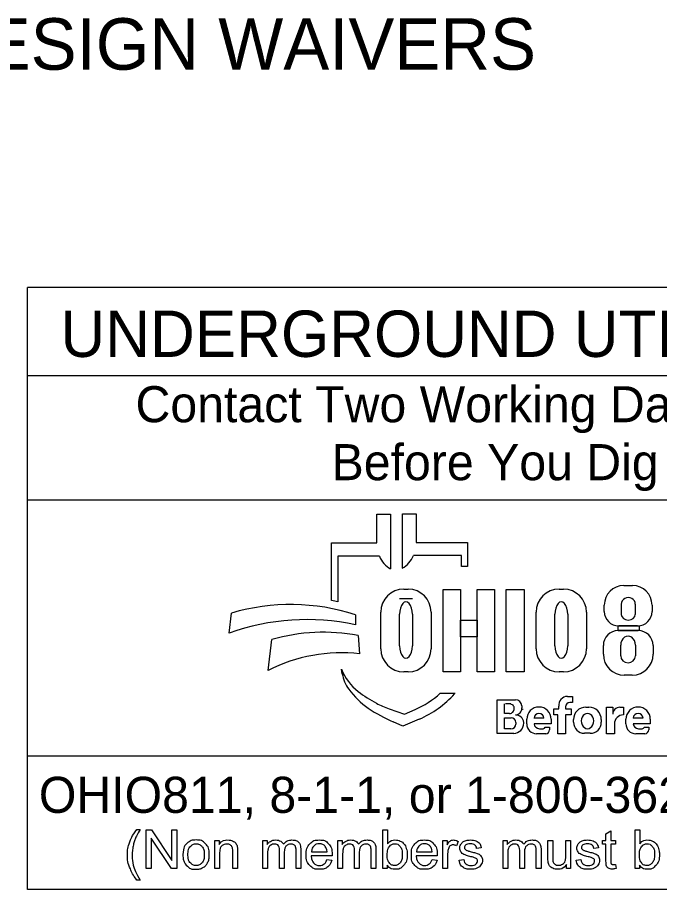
# Model space of a CAD drawing. Extents: x 0 to 34, y 0 to 22.
# Drawn here: x 2.939 to 5.431, y 2.143 to 5.529 of the extents above; entities that cross this region are included whole.
import ezdxf

# ---------------------------------------------------------------- set-up
doc = ezdxf.new("R2010")
doc.units = 0
doc.layers.add('SH_Data', color=7, linetype='Continuous')
doc.layers.add('SH_Text', color=7, linetype='Continuous')

msp = doc.modelspace()

# ---------------------------------------------------------------- linework, layer by layer
at = {"layer": 'SH_Data'}
for p, q in [((2.9775, 2.1428), (2.9775, 4.4803)), ((7.2275, 4.4803), (2.9775, 4.4803)), ((2.9775, 4.1387), (7.2275, 4.1387)), ((2.9775, 3.6553), (7.2275, 3.6553)), ((7.2275, 2.6607), (2.9775, 2.6607)), ((7.2275, 2.1428), (2.9775, 2.1428))]:
    msp.add_line(p, q, dxfattribs=at)
at = {"layer": 'SH_Text'}
for p, q in [((4.3335, 3.4883), (4.3335, 3.5998)), ((4.3335, 3.5998), (4.3872, 3.5998)), ((4.3872, 3.5998), (4.3872, 3.3877)), ((4.4329, 3.39), (4.4329, 3.6021)), ((4.4329, 3.6021), (4.4865, 3.6021)), ((4.4865, 3.6021), (4.4865, 3.4906)), ((4.1576, 3.2644), (4.1576, 3.4883)), ((4.1576, 3.4883), (4.3335, 3.4883)), ((4.4865, 3.4906), (4.6857, 3.4906)), ((4.6857, 3.4906), (4.6857, 3.3968)), ((4.1828, 3.4369), (4.1828, 3.26)), ((4.3439, 3.4369), (4.1828, 3.4369)), ((4.6625, 3.4392), (4.4761, 3.4392)), ((4.6625, 3.3968), (4.6625, 3.4392)), ((4.6857, 3.3968), (4.6625, 3.3968)), ((5.2931, 3.3231), (5.3258, 3.3231)), ((4.4385, 3.3091), (4.4551, 3.3091)), ((5.0416, 3.3091), (5.0581, 3.3091)), ((4.4718, 3.2721), (4.422, 3.2721)), ((5.283, 3.2111), (5.283, 3.2504)), ((5.3371, 3.2504), (5.3371, 3.2111)), ((4.3491, 3.0776), (4.3491, 3.2196)), ((4.5445, 3.2196), (4.5445, 3.0776)), ((4.9521, 3.0776), (4.9521, 3.2196)), ((5.1476, 3.2196), (5.1476, 3.0776)), ((5.2168, 3.2225), (5.2168, 3.2468)), ((5.4022, 3.2468), (5.4022, 3.2225)), ((3.7602, 3.1381), (3.7696, 3.2162)), ((4.2509, 3.2097), (4.2509, 3.1709)), ((4.422, 3.089), (4.422, 3.2114)), ((4.4718, 3.2114), (4.4718, 3.089)), ((5.025, 3.089), (5.025, 3.2114)), ((5.0748, 3.2114), (5.0748, 3.089)), ((5.3462, 3.1665), (5.2728, 3.1665)), ((4.2608, 3.1291), (4.2671, 3.0582)), ((5.271, 3.1482), (5.3483, 3.1482)), ((3.912, 2.9936), (3.9267, 3.1137)), ((5.2131, 3.0563), (5.2131, 3.0903)), ((5.2806, 3.0503), (5.2806, 3.0912)), ((5.3374, 3.0912), (5.3374, 3.0503)), ((5.4062, 3.0903), (5.4062, 3.0563)), ((4.1997, 2.9807), (4.1967, 2.9986)), ((4.4551, 2.9882), (4.4385, 2.9882)), ((5.0581, 2.9882), (5.0416, 2.9882)), ((5.3252, 2.9753), (5.2941, 2.9753)), ((4.58, 2.9048), (4.6375, 2.9048)), ((4.8013, 2.749), (4.8013, 2.8798)), ((4.8013, 2.8798), (4.8725, 2.8798)), ((5.0739, 2.8926), (5.0934, 2.8926)), ((5.0934, 2.8926), (5.0934, 2.8696)), ((4.3816, 2.8444), (4.441, 2.8239)), ((4.8293, 2.8263), (4.8293, 2.8632)), ((4.8545, 2.8632), (4.8332, 2.8632)), ((4.8963, 2.856), (4.8963, 2.8481)), ((5.0213, 2.8212), (5.0213, 2.8442)), ((5.0213, 2.8442), (5.0406, 2.8442)), ((5.0406, 2.8442), (5.0406, 2.8546)), ((5.0667, 2.8526), (5.0667, 2.8442)), ((5.0667, 2.8442), (5.0883, 2.8442)), ((5.0934, 2.8691), (5.0832, 2.8691)), ((5.0883, 2.8442), (5.0883, 2.8212)), ((5.1451, 2.8508), (5.1573, 2.8508)), ((5.2254, 2.7478), (5.2254, 2.8505)), ((5.2254, 2.8505), (5.2499, 2.8505)), ((5.2499, 2.8505), (5.2499, 2.8237)), ((5.2772, 2.8505), (5.291, 2.8505)), ((5.291, 2.8505), (5.291, 2.8209)), ((4.441, 2.8239), (4.4821, 2.8417)), ((4.8487, 2.8263), (4.8293, 2.8263)), ((5.0362, 2.8212), (5.0213, 2.8212)), ((5.0362, 2.7478), (5.0362, 2.8212)), ((5.0883, 2.8212), (5.0667, 2.8212)), ((5.0667, 2.8212), (5.0667, 2.7478)), ((4.435, 2.7769), (4.3976, 2.7934)), ((4.4983, 2.8044), (4.435, 2.7769)), ((4.8293, 2.7669), (4.8293, 2.8097)), ((4.8293, 2.8097), (4.8548, 2.8097)), ((4.8729, 2.7916), (4.8729, 2.7853)), ((4.9043, 2.7887), (4.9043, 2.7884)), ((4.9159, 2.7858), (4.9159, 2.8042)), ((4.9824, 2.8082), (4.9439, 2.8082)), ((5.0104, 2.7866), (4.944, 2.7866)), ((5.0104, 2.8042), (5.0104, 2.7866)), ((5.0973, 2.7922), (5.0973, 2.8029)), ((5.2051, 2.8029), (5.2051, 2.7922)), ((5.2559, 2.786), (5.2559, 2.7478)), ((5.3008, 2.7858), (5.3008, 2.8042)), ((5.3674, 2.8082), (5.3288, 2.8082)), ((5.3953, 2.7866), (5.3289, 2.7866)), ((5.3953, 2.8042), (5.3953, 2.7866)), ((4.865, 2.749), (4.8013, 2.749)), ((4.8546, 2.7669), (4.8293, 2.7669)), ((4.9892, 2.7478), (4.9538, 2.7478)), ((4.9649, 2.7673), (4.979, 2.7673)), ((4.9876, 2.7729), (5.0045, 2.7729)), ((5.0045, 2.7729), (5.0045, 2.7631)), ((5.0667, 2.7478), (5.0362, 2.7478)), ((5.1623, 2.7494), (5.1401, 2.7494)), ((5.2559, 2.7478), (5.2254, 2.7478)), ((5.3742, 2.7478), (5.3388, 2.7478)), ((5.3498, 2.7673), (5.3639, 2.7673)), ((5.3725, 2.7729), (5.3894, 2.7729)), ((5.3894, 2.7729), (5.3894, 2.7631))]:
    msp.add_line(p, q, dxfattribs=at)
for points in [[(4.591, 3.3081), (4.6589, 3.3081), (4.6589, 2.9881), (4.591, 2.9881)], [(4.7231, 3.3081), (4.7911, 3.3081), (4.7911, 2.9881), (4.7231, 2.9881)], [(4.8364, 3.3081), (4.9052, 3.3081), (4.9052, 2.9881), (4.8364, 2.9881)], [(4.6589, 3.1882), (4.7231, 3.1882), (4.7231, 3.1242), (4.6589, 3.1242)], [(5.2706, 3.1665), (5.3523, 3.1665), (5.3523, 3.1481), (5.2706, 3.1481)]]:
    msp.add_lwpolyline(points, close=True, dxfattribs=at)
for points in [[(3.4021, 2.3766), (3.4153, 2.3766)], [(3.4389, 2.2239), (3.4389, 2.3741), (3.4592, 2.3741), (3.5382, 2.2561), (3.5382, 2.3741), (3.5572, 2.3741), (3.5572, 2.2239), (3.5369, 2.2239), (3.4579, 2.3419), (3.4579, 2.2239), (3.4389, 2.2239)], [(4.3743, 2.2239), (4.3573, 2.2239), (4.3573, 2.3741), (4.3757, 2.3741), (4.3757, 2.3206)], [(5.2233, 2.2558), (5.2233, 2.3185), (5.2097, 2.3185), (5.2097, 2.3328), (5.2233, 2.3328), (5.2233, 2.3597), (5.2417, 2.3708), (5.2417, 2.3328), (5.2601, 2.3328), (5.2601, 2.3185), (5.2417, 2.3185), (5.2417, 2.2547)], [(5.3534, 2.2239), (5.3363, 2.2239), (5.3363, 2.3741), (5.3548, 2.3741), (5.3548, 2.3206)], [(3.7048, 2.2239), (3.7048, 2.3328), (3.7214, 2.3328), (3.7214, 2.3173)], [(3.8912, 2.2239), (3.8912, 2.3328), (3.9077, 2.3328), (3.9077, 2.3174)], [(4.1826, 2.2239), (4.1826, 2.3328), (4.1991, 2.3328), (4.1991, 2.3174)], [(4.5904, 2.2239), (4.5904, 2.3328), (4.607, 2.3328), (4.607, 2.3163)], [(4.6495, 2.3293), (4.643, 2.3122)], [(4.7394, 2.3046), (4.7213, 2.3022)], [(4.8236, 2.2239), (4.8236, 2.3328), (4.8401, 2.3328), (4.8401, 2.3174)], [(4.9979, 2.2654), (4.9979, 2.3328), (5.0164, 2.3328), (5.0164, 2.2724)], [(5.0676, 2.2745), (5.0676, 2.3328), (5.0861, 2.3328), (5.0861, 2.2239), (5.0696, 2.2239)], [(5.194, 2.3046), (5.1759, 2.3022)], [(3.7233, 2.2833), (3.7233, 2.2239), (3.7048, 2.2239)], [(3.7932, 2.2908), (3.7932, 2.2239), (3.7748, 2.2239), (3.7748, 2.2901)], [(3.9097, 2.2803), (3.9097, 2.2239), (3.8912, 2.2239)], [(3.9743, 2.2871), (3.9743, 2.2239), (3.9559, 2.2239), (3.9559, 2.2946)], [(4.0388, 2.2986), (4.0388, 2.2239), (4.0203, 2.2239), (4.0203, 2.2924)], [(4.16, 2.2736), (4.0788, 2.2736)], [(4.0799, 2.2887), (4.1406, 2.2887)], [(4.201, 2.2803), (4.201, 2.2239), (4.1826, 2.2239)], [(4.2657, 2.2871), (4.2657, 2.2239), (4.2473, 2.2239), (4.2473, 2.2946)], [(4.3301, 2.2986), (4.3301, 2.2239), (4.3117, 2.2239), (4.3117, 2.2924)], [(4.568, 2.2736), (4.4868, 2.2736)], [(4.4879, 2.2887), (4.5486, 2.2887)], [(4.6088, 2.2809), (4.6088, 2.2239), (4.5904, 2.2239)], [(4.842, 2.2803), (4.842, 2.2239), (4.8236, 2.2239)], [(4.9067, 2.2871), (4.9067, 2.2239), (4.8883, 2.2239), (4.8883, 2.2946)], [(4.9711, 2.2986), (4.9711, 2.2239), (4.9527, 2.2239), (4.9527, 2.2924)], [(4.1404, 2.2591), (4.1595, 2.2567)], [(4.3743, 2.2375), (4.3743, 2.2239)], [(4.5484, 2.2591), (4.5675, 2.2567)], [(4.653, 2.2564), (4.6712, 2.2593)], [(5.0696, 2.2239), (5.0696, 2.24)], [(5.1076, 2.2564), (5.1258, 2.2593)], [(5.2601, 2.2404), (5.2628, 2.2241)], [(5.3534, 2.2375), (5.3534, 2.2239)], [(3.4153, 2.1798), (3.4021, 2.1798)]]:
    msp.add_lwpolyline(points, dxfattribs=at)
for centre, radius, start, end in [((4.4353, 3.4736), 0.0985, 201.9296, 240.7469), ((4.3847, 3.476), 0.0985, 299.2531, 338.0704), ((5.2931, 3.2468), 0.0763, 90, 180), ((5.3258, 3.2468), 0.0763, 0, 90), ((4.4385, 3.2196), 0.0895, 90, 180), ((4.4551, 3.2196), 0.0895, 0, 90), ((5.0416, 3.2196), 0.0895, 90, 180), ((5.0581, 3.2196), 0.0895, 0, 90), ((4.0295, 2.4554), 0.8191, 79.2074, 81.0007), ((3.9997, 2.4302), 0.8191, 72.1402, 106.3144), ((5.2728, 3.2225), 0.056, 180, 270), ((5.3462, 3.2225), 0.056, 270, 0), ((4.0628, 2.2991), 0.8919, 77.8238, 109.8274), ((4.1267, 2.4094), 0.7322, 79.44, 105.8467), ((5.271, 3.0903), 0.0579, 90, 180), ((5.3483, 3.0903), 0.0579, 0, 90), ((4.1987, 2.4262), 0.6357, 83.8248, 116.8021), ((4.4385, 3.0776), 0.0895, 180, 270), ((4.4551, 3.0776), 0.0895, 270, 0), ((5.0416, 3.0776), 0.0895, 180, 270), ((5.0581, 3.0776), 0.0895, 270, 0), ((5.2941, 3.0563), 0.081, 180, 270), ((5.3252, 3.0563), 0.081, 270, 0), ((4.3841, 3.0707), 0.2008, 201.0457, 232.5314), ((4.341, 3.0048), 0.1433, 189.6817, 216.0884), ((4.4747, 3.1022), 0.3088, 216.0884, 235.7167), ((4.5766, 3.3219), 0.5173, 232.5314, 241.794), ((4.3387, 3.1722), 0.3602, 293.4582, 312.0712), ((4.3387, 3.1722), 0.401, 293.4582, 317.8286), ((4.8725, 2.856), 0.0238, 0, 90), ((5.0739, 2.859), 0.0335, 90, 187.5187), ((4.6412, 3.3465), 0.6044, 235.7167, 246.2325), ((4.4914, 3.1631), 0.3371, 241.794, 250.9821), ((4.8487, 2.845), 0.0187, 270, 2.0582), ((4.8505, 2.8463), 0.0169, 357.8325, 90), ((4.8721, 2.8453), 0.0243, 270, 6.6529), ((4.9631, 2.8042), 0.0473, 0, 180), ((5.0832, 2.8526), 0.0165, 90, 180), ((5.1451, 2.8029), 0.0478, 90, 180), ((5.1573, 2.8029), 0.0478, 0, 90), ((5.2768, 2.8237), 0.0269, 89.2449, 180), ((5.3481, 2.8042), 0.0473, 0, 180), ((4.8722, 2.7889), 0.0321, 4.0748, 90), ((4.8827, 2.8438), 0.0175, 347.4023, 0), ((4.9632, 2.8072), 0.0193, 2.9632, 177.0368), ((5.2908, 2.786), 0.0349, 89.6033, 180), ((5.3481, 2.8072), 0.0193, 2.9632, 177.0368), ((4.8546, 2.7853), 0.0184, 270, 0), ((4.8548, 2.7916), 0.0181, 0, 90), ((4.865, 2.7884), 0.0393, 270, 0), ((4.8714, 2.7887), 0.033, 0, 11.7502), ((4.9538, 2.7858), 0.038, 180, 270), ((4.9649, 2.7883), 0.021, 184.827, 270), ((5.1401, 2.7922), 0.0428, 180, 270), ((5.1623, 2.7922), 0.0428, 270, 0), ((5.3388, 2.7858), 0.038, 180, 270), ((5.3498, 2.7883), 0.021, 184.827, 270), ((4.979, 2.7767), 0.00938, 270, 335.9979), ((4.9892, 2.7631), 0.0152, 270, 0), ((5.3639, 2.7767), 0.00938, 270, 335.9979), ((5.3742, 2.7631), 0.0152, 270, 0)]:
    msp.add_arc(centre, radius, start, end, dxfattribs=at)
for centre, major_axis, ratio, start_param, end_param in [((4.4469, 3.2114), (0, 0.0484), 0.514403, 4.712389, 7.853982), ((5.0499, 3.2114), (0, 0.0484), 0.514403, 4.712389, 7.853982), ((5.31, 3.2504), (0.0271, 0), 0.969373, 0, 3.141593), ((5.31, 3.2111), (0.0271, 0), 0.818453, 3.141593, 6.283185), ((5.309, 3.0912), (0, 0.0358), 0.794529, 4.712389, 7.853982), ((4.4469, 3.089), (0, 0.0484), 0.514403, 1.570796, 4.712389), ((5.0499, 3.089), (0, 0.0484), 0.514403, 1.570796, 4.712389), ((5.309, 3.0503), (0.0284, 0), 0.959837, 3.141593, 6.283185), ((5.1517, 2.7976), (0, 0.029), 0.832186, 4.712389, 7.853982), ((5.1517, 2.7976), (0, 0.0302), 0.797287, 1.570796, 4.712389)]:
    msp.add_ellipse(centre, major_axis=major_axis, ratio=ratio, start_param=start_param, end_param=end_param, dxfattribs=at)
for points in [[(3.4021, 2.1798), (3.3869, 2.199), (3.3763, 2.2248), (3.3657, 2.2506), (3.3657, 2.2783), (3.3657, 2.3026), (3.3736, 2.325), (3.3829, 2.3509), (3.4021, 2.3766)], [(3.4153, 2.3766), (3.4029, 2.3553), (3.3989, 2.3462), (3.3927, 2.332), (3.3891, 2.3167), (3.3847, 2.2975), (3.3847, 2.2782), (3.3847, 2.2289), (3.4153, 2.1798)], [(3.5814, 2.2783), (3.5814, 2.3085), (3.5981, 2.3231), (3.6122, 2.3352), (3.6323, 2.3352), (3.6547, 2.3352), (3.669, 2.3205), (3.6832, 2.3058), (3.6832, 2.2799), (3.6832, 2.2589), (3.6769, 2.2469), (3.6706, 2.2348), (3.6586, 2.2282), (3.6466, 2.2215), (3.6323, 2.2215), (3.6095, 2.2215), (3.5954, 2.2362), (3.5814, 2.2508), (3.5814, 2.2783)], [(3.6003, 2.2783), (3.6003, 2.2574), (3.6094, 2.247), (3.6185, 2.2366), (3.6323, 2.2366), (3.646, 2.2366), (3.6551, 2.2471), (3.6642, 2.2575), (3.6642, 2.279), (3.6642, 2.2991), (3.6551, 2.3095), (3.6459, 2.3199), (3.6323, 2.3199), (3.6185, 2.3199), (3.6094, 2.3096), (3.6003, 2.2992), (3.6003, 2.2783)], [(3.7214, 2.3173), (3.7334, 2.3352), (3.756, 2.3352), (3.7659, 2.3352), (3.7741, 2.3316), (3.7823, 2.3281), (3.7864, 2.3224), (3.7905, 2.3166), (3.7922, 2.3087), (3.7932, 2.3036), (3.7932, 2.2908)], [(3.7748, 2.2901), (3.7748, 2.3013), (3.7726, 2.3069), (3.7705, 2.3125), (3.765, 2.3158), (3.7595, 2.3191), (3.7521, 2.3191), (3.7404, 2.3191), (3.7318, 2.3117), (3.7233, 2.3042), (3.7233, 2.2833)], [(3.9077, 2.3174), (3.9128, 2.3254), (3.9214, 2.3303), (3.9299, 2.3352), (3.9407, 2.3352), (3.9528, 2.3352), (3.9606, 2.3301), (3.9683, 2.3251), (3.9715, 2.3161), (3.9844, 2.3352), (4.0051, 2.3352), (4.0213, 2.3352), (4.03, 2.3262), (4.0388, 2.3172), (4.0388, 2.2986)], [(3.9559, 2.2946), (3.9559, 2.3069), (3.9514, 2.313), (3.9469, 2.3191), (3.9366, 2.3191), (3.9288, 2.3191), (3.9222, 2.315), (3.9156, 2.311), (3.9126, 2.3031), (3.9097, 2.2952), (3.9097, 2.2803)], [(4.0203, 2.2924), (4.0203, 2.3035), (4.0185, 2.3083), (4.0168, 2.3132), (4.012, 2.3162), (4.0073, 2.3191), (4.001, 2.3191), (3.9895, 2.3191), (3.9819, 2.3115), (3.9743, 2.3039), (3.9743, 2.2871)], [(4.1595, 2.2567), (4.155, 2.24), (4.1428, 2.2307), (4.1306, 2.2215), (4.1117, 2.2215), (4.0878, 2.2215), (4.0738, 2.2362), (4.0598, 2.2509), (4.0598, 2.2774), (4.0598, 2.3049), (4.074, 2.32), (4.0881, 2.3352), (4.1106, 2.3352), (4.1324, 2.3352), (4.1463, 2.3203), (4.1601, 2.3055), (4.1601, 2.2785), (4.1601, 2.2769), (4.16, 2.2736)], [(4.1406, 2.2887), (4.1394, 2.3025), (4.1337, 2.3094), (4.1249, 2.3201), (4.1108, 2.3201), (4.0981, 2.3201), (4.0894, 2.3115), (4.0808, 2.303), (4.0799, 2.2887)], [(4.1991, 2.3174), (4.2042, 2.3254), (4.2127, 2.3303), (4.2212, 2.3352), (4.2321, 2.3352), (4.2442, 2.3352), (4.2519, 2.3301), (4.2597, 2.3251), (4.2628, 2.3161), (4.2758, 2.3352), (4.2965, 2.3352), (4.3127, 2.3352), (4.3214, 2.3262), (4.3301, 2.3172), (4.3301, 2.2986)], [(4.2473, 2.2946), (4.2473, 2.3069), (4.2428, 2.313), (4.2383, 2.3191), (4.228, 2.3191), (4.2202, 2.3191), (4.2136, 2.315), (4.207, 2.311), (4.204, 2.3031), (4.201, 2.2952), (4.201, 2.2803)], [(4.3117, 2.2924), (4.3117, 2.3035), (4.3099, 2.3083), (4.3081, 2.3132), (4.3034, 2.3162), (4.2987, 2.3191), (4.2923, 2.3191), (4.2809, 2.3191), (4.2733, 2.3115), (4.2657, 2.3039), (4.2657, 2.2871)], [(4.3741, 2.2792), (4.3741, 2.2596), (4.3794, 2.2509), (4.3881, 2.2366), (4.4029, 2.2366), (4.415, 2.2366), (4.4238, 2.2471), (4.4326, 2.2576), (4.4326, 2.2784), (4.4326, 2.2998), (4.4241, 2.3099), (4.4157, 2.3201), (4.4038, 2.3201), (4.3917, 2.3201), (4.3829, 2.3096), (4.3741, 2.299), (4.3741, 2.2792)], [(4.3757, 2.3206), (4.3874, 2.3352), (4.4055, 2.3352), (4.4155, 2.3352), (4.4245, 2.3311), (4.4335, 2.3271), (4.4392, 2.3198), (4.445, 2.3124), (4.4483, 2.3021), (4.4516, 2.2918), (4.4516, 2.28), (4.4516, 2.252), (4.4378, 2.2368), (4.4239, 2.2215), (4.4046, 2.2215), (4.3853, 2.2215), (4.3743, 2.2375)], [(4.5675, 2.2567), (4.563, 2.24), (4.5508, 2.2307), (4.5386, 2.2215), (4.5196, 2.2215), (4.4958, 2.2215), (4.4818, 2.2362), (4.4678, 2.2509), (4.4678, 2.2774), (4.4678, 2.3049), (4.482, 2.32), (4.4961, 2.3352), (4.5186, 2.3352), (4.5404, 2.3352), (4.5543, 2.3203), (4.5681, 2.3055), (4.5681, 2.2785), (4.5681, 2.2769), (4.568, 2.2736)], [(4.5486, 2.2887), (4.5474, 2.3025), (4.5417, 2.3094), (4.5328, 2.3201), (4.5188, 2.3201), (4.5061, 2.3201), (4.4974, 2.3115), (4.4888, 2.303), (4.4879, 2.2887)], [(4.607, 2.3163), (4.6133, 2.3278), (4.6187, 2.3315), (4.6241, 2.3352), (4.6305, 2.3352), (4.6398, 2.3352), (4.6495, 2.3293)], [(4.643, 2.3122), (4.6363, 2.3162), (4.6295, 2.3162), (4.6235, 2.3162), (4.6187, 2.3125), (4.6139, 2.3089), (4.6119, 2.3024), (4.6088, 2.2926), (4.6088, 2.2809)], [(4.7213, 2.3022), (4.7201, 2.3106), (4.7142, 2.3153), (4.7083, 2.3201), (4.6975, 2.3201), (4.6848, 2.3201), (4.6794, 2.3159), (4.6739, 2.3116), (4.6739, 2.306), (4.6739, 2.3024), (4.6762, 2.2995), (4.6785, 2.2966), (4.6833, 2.2946), (4.686, 2.2936), (4.6996, 2.2899), (4.7192, 2.2847), (4.7269, 2.2813), (4.7347, 2.278), (4.7391, 2.2717), (4.7435, 2.2653), (4.7435, 2.2559), (4.7435, 2.2467), (4.7381, 2.2386), (4.7327, 2.2304), (4.7226, 2.226), (4.7124, 2.2215), (4.6996, 2.2215), (4.6784, 2.2215), (4.6672, 2.2303), (4.6561, 2.2391), (4.653, 2.2564)], [(4.6712, 2.2593), (4.6727, 2.2483), (4.6798, 2.2425), (4.6868, 2.2366), (4.6995, 2.2366), (4.7122, 2.2366), (4.7184, 2.2418), (4.7245, 2.247), (4.7245, 2.254), (4.7245, 2.2602), (4.7191, 2.2638), (4.7153, 2.2663), (4.7002, 2.2701), (4.6799, 2.2752), (4.672, 2.2789), (4.6642, 2.2827), (4.6601, 2.2893), (4.6561, 2.2959), (4.6561, 2.3038), (4.6561, 2.3111), (4.6594, 2.3173), (4.6628, 2.3235), (4.6685, 2.3276), (4.6728, 2.3308), (4.6803, 2.333), (4.6877, 2.3352), (4.6962, 2.3352), (4.709, 2.3352), (4.7187, 2.3315), (4.7284, 2.3278), (4.733, 2.3215), (4.7377, 2.3152), (4.7394, 2.3046)], [(4.8401, 2.3174), (4.8452, 2.3254), (4.8537, 2.3303), (4.8622, 2.3352), (4.8731, 2.3352), (4.8852, 2.3352), (4.8929, 2.3301), (4.9007, 2.3251), (4.9038, 2.3161), (4.9168, 2.3352), (4.9375, 2.3352), (4.9537, 2.3352), (4.9624, 2.3262), (4.9711, 2.3172), (4.9711, 2.2986)], [(4.8883, 2.2946), (4.8883, 2.3069), (4.8838, 2.313), (4.8793, 2.3191), (4.869, 2.3191), (4.8612, 2.3191), (4.8546, 2.315), (4.848, 2.311), (4.845, 2.3031), (4.842, 2.2952), (4.842, 2.2803)], [(4.9527, 2.2924), (4.9527, 2.3035), (4.9509, 2.3083), (4.9491, 2.3132), (4.9444, 2.3162), (4.9397, 2.3191), (4.9333, 2.3191), (4.9219, 2.3191), (4.9143, 2.3115), (4.9067, 2.3039), (4.9067, 2.2871)], [(5.1759, 2.3022), (5.1747, 2.3106), (5.1688, 2.3153), (5.1629, 2.3201), (5.1521, 2.3201), (5.1394, 2.3201), (5.1339, 2.3159), (5.1285, 2.3116), (5.1285, 2.306), (5.1285, 2.3024), (5.1308, 2.2995), (5.133, 2.2966), (5.1378, 2.2946), (5.1406, 2.2936), (5.1542, 2.2899), (5.1737, 2.2847), (5.1815, 2.2813), (5.1893, 2.278), (5.1937, 2.2717), (5.1981, 2.2653), (5.1981, 2.2559), (5.1981, 2.2467), (5.1927, 2.2386), (5.1873, 2.2304), (5.1772, 2.226), (5.167, 2.2215), (5.1542, 2.2215), (5.1329, 2.2215), (5.1218, 2.2303), (5.1107, 2.2391), (5.1076, 2.2564)], [(5.1258, 2.2593), (5.1273, 2.2483), (5.1343, 2.2425), (5.1414, 2.2366), (5.154, 2.2366), (5.1668, 2.2366), (5.1729, 2.2418), (5.1791, 2.247), (5.1791, 2.254), (5.1791, 2.2602), (5.1736, 2.2638), (5.1698, 2.2663), (5.1548, 2.2701), (5.1345, 2.2752), (5.1266, 2.2789), (5.1188, 2.2827), (5.1147, 2.2893), (5.1107, 2.2959), (5.1107, 2.3038), (5.1107, 2.3111), (5.114, 2.3173), (5.1173, 2.3235), (5.1231, 2.3276), (5.1274, 2.3308), (5.1348, 2.333), (5.1423, 2.3352), (5.1508, 2.3352), (5.1636, 2.3352), (5.1733, 2.3315), (5.183, 2.3278), (5.1876, 2.3215), (5.1922, 2.3152), (5.194, 2.3046)], [(5.3532, 2.2792), (5.3532, 2.2596), (5.3585, 2.2509), (5.3672, 2.2366), (5.382, 2.2366), (5.3941, 2.2366), (5.4029, 2.2471), (5.4116, 2.2576), (5.4116, 2.2784), (5.4116, 2.2998), (5.4032, 2.3099), (5.3948, 2.3201), (5.3828, 2.3201), (5.3708, 2.3201), (5.362, 2.3096), (5.3532, 2.299), (5.3532, 2.2792)], [(5.3548, 2.3206), (5.3664, 2.3352), (5.3846, 2.3352), (5.3946, 2.3352), (5.4036, 2.3311), (5.4125, 2.3271), (5.4183, 2.3198), (5.4241, 2.3124), (5.4274, 2.3021), (5.4306, 2.2918), (5.4306, 2.28), (5.4306, 2.252), (5.4168, 2.2368), (5.403, 2.2215), (5.3836, 2.2215), (5.3644, 2.2215), (5.3534, 2.2375)], [(4.0788, 2.2736), (4.0799, 2.2557), (4.089, 2.2462), (4.0981, 2.2366), (4.1117, 2.2366), (4.1219, 2.2366), (4.1291, 2.242), (4.1362, 2.2473), (4.1404, 2.2591)], [(4.4868, 2.2736), (4.4879, 2.2557), (4.497, 2.2462), (4.5061, 2.2366), (4.5197, 2.2366), (4.5299, 2.2366), (4.537, 2.242), (4.5442, 2.2473), (4.5484, 2.2591)], [(5.0164, 2.2724), (5.0164, 2.258), (5.0175, 2.253), (5.0192, 2.2457), (5.0249, 2.2416), (5.0305, 2.2374), (5.0388, 2.2374), (5.0471, 2.2374), (5.0543, 2.2417), (5.0616, 2.2459), (5.0646, 2.2533), (5.0676, 2.2606), (5.0676, 2.2745)], [(5.0696, 2.24), (5.0569, 2.2215), (5.0351, 2.2215), (5.0255, 2.2215), (5.0171, 2.2252), (5.0088, 2.2289), (5.0047, 2.2345), (5.0007, 2.2401), (4.9991, 2.2482), (4.9979, 2.2536), (4.9979, 2.2654)], [(5.2628, 2.2241), (5.255, 2.2224), (5.2488, 2.2224), (5.2388, 2.2224), (5.2333, 2.2256), (5.2278, 2.2288), (5.2255, 2.234), (5.2233, 2.2392), (5.2233, 2.2558)], [(5.2417, 2.2547), (5.2417, 2.2468), (5.2427, 2.2445), (5.2436, 2.2423), (5.2458, 2.2409), (5.248, 2.2396), (5.2521, 2.2396), (5.2551, 2.2396), (5.2601, 2.2404)]]:
    msp.add_open_spline(points, degree=3, dxfattribs=at)

# ---------------------------------------------------------------- texts
for s, height, p in [('ADA DESIGN WAIVERS', 0.2, (1.9944, 5.3256)), ('UNDERGROUND UTILITIES', 0.18, (3.1057, 4.2106)), ('Contact Two Working Days', 0.14, (3.3972, 3.9571)), ('Before You Dig', 0.14, (4.1583, 3.7321)), ('OHIO811, 8-1-1, or 1-800-362-2764', 0.14, (3.022, 2.4406))]:
    msp.add_text(s, height=height, dxfattribs=at).set_placement(p)

doc.saveas('drawing.dxf')
